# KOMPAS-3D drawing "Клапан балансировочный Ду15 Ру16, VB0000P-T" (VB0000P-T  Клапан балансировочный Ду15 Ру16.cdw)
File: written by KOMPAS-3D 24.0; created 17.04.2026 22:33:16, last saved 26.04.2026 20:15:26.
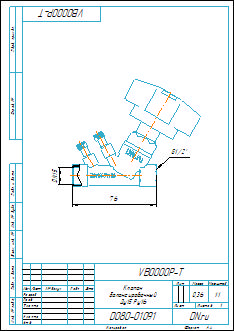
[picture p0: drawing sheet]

Document properties: Автор: tyuri; Форматы листов документа: A4; Полное имя файла: VB0000P-T Клапан балансировочный Ду15 Ру16.m3d; Масса: 0.36; Наименование: Клапан балансировочный Ду15 Ру16; Количество листов документа: 1; Примечание: D080-01091

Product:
- Part/product: Клапан балансировочный Ду15 Ру16  | designation VB0000P-T
    Масса: 0.36
    Раздел спецификации: Прочие изделия
    Примечание: D080-01091

Referenced files in D:\Аутсорс\VB0000P-T Клапан балансировочный статический DN.ru\DN15\: VB0000P-T  Клапан балансировочный статический Ду15 Ру16.cdw
Referenced files in E:\Работа\Зайцев\АУТСОРС\Диман\Балансировка\VB0000P-T Клапан балансировочный DN.ru Ду15-50 Ру16\DN15\: VB0000P-T Клапан балансировочный Ду15 Ру16.m3d
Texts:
  Клапан
  балансировочный
  Ду15 Ру16
  VB0000P-T
  Клапан балансировочный Ду15 Ру16
  VB0000P-T Клапан балансировочный Ду15 Ру16
Dimensions and other numbers on the sheet: 1:1; 0; 1; 2; 0,36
